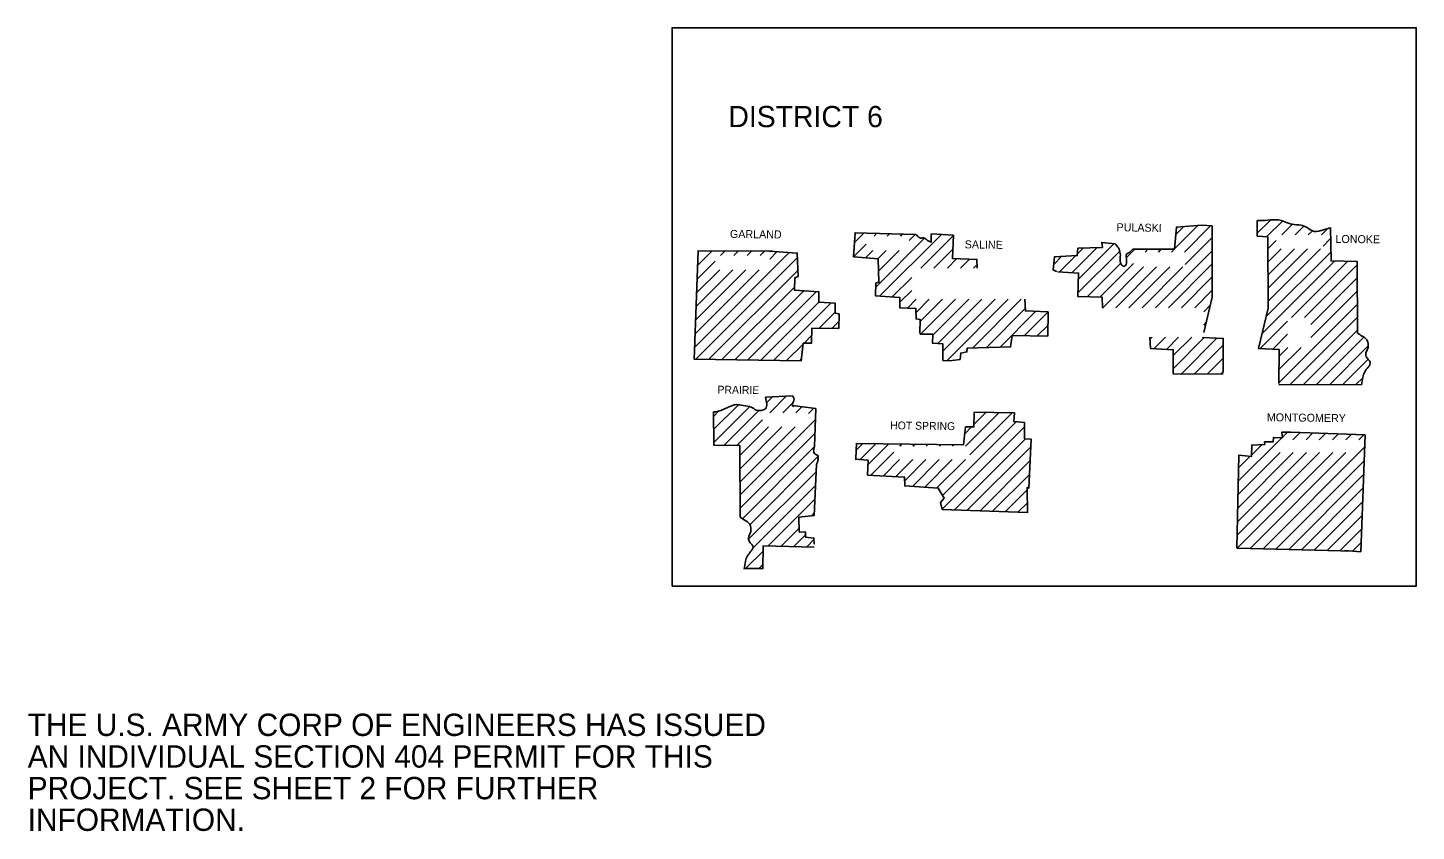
# Model space of a CAD drawing. Extents: x 76 to 6945, y -3933 to 2152.
# Drawn here: x 5990 to 6737, y -2877 to -2445 of the extents above; entities that cross this region are included whole.
import ezdxf

# ---------------------------------------------------------------- set-up
doc = ezdxf.new("R2010")
doc.units = 0
doc.layers.add('R_Draft', color=7, linetype='Continuous')

msp = doc.modelspace()

# ---------------------------------------------------------------- linework, layer by layer
at = {"layer": 'R_Draft'}
for p, q in [((6475.91, -2560.12), (6475.91, -2555.72)), ((6442.11, -2677.32), (6435.01, -2676.62))]:
    msp.add_line(p, q, dxfattribs=at)
msp.add_lwpolyline([(6336.61, -2744.92), (6336.61, -2444.92), (6736.61, -2444.92), (6736.61, -2744.92)], close=True, dxfattribs=at)
for points in [[(6584.21, -2563.92), (6606.71, -2563.82), (6607.71, -2552.02), (6621.11, -2551.02)], [(6606.71, -2563.72), (6619.31, -2551.12)], [(6607.41, -2556.02), (6611.71, -2551.72)], [(6612.11, -2565.42), (6626.11, -2551.42)], [(6621.11, -2551.02), (6626.91, -2551.42), (6627.01, -2589.62), (6622.41, -2608.72)], [(6651.11, -2555.32), (6658.21, -2548.32)], [(6651.11, -2556.92), (6651.11, -2548.52)], [(6656.21, -2557.32), (6664.71, -2548.82)], [(6664.41, -2556.22), (6670.11, -2550.52)], [(6671.51, -2556.22), (6676.11, -2551.62)], [(6690.61, -2552.32), (6690.81, -2570.22), (6704.91, -2570.52), (6705.01, -2608.92)], [(6434.11, -2567.92), (6435.01, -2555.02), (6467.71, -2556.02)], [(6434.61, -2560.32), (6439.81, -2555.12)], [(6445.21, -2556.82), (6446.71, -2555.32)], [(6446.11, -2584.22), (6472.11, -2558.12)], [(6448.31, -2589.02), (6481.21, -2556.12)], [(6452.31, -2556.82), (6453.41, -2555.62)], [(6459.41, -2556.82), (6460.31, -2555.82)], [(6464.01, -2559.22), (6467.21, -2556.02)], [(6470.41, -2574.02), (6487.71, -2556.72)], [(6475.91, -2555.72), (6487.81, -2556.42), (6487.41, -2568.92), (6500.51, -2569.42), (6500.61, -2574.02)], [(6612.41, -2572.12), (6626.91, -2557.62)], [(6662.81, -2636.12), (6662.91, -2617.72), (6651.81, -2617.22), (6657.01, -2595.52), (6656.91, -2557.32), (6651.11, -2556.92)], [(6656.91, -2563.72), (6661.41, -2559.22)], [(6678.61, -2556.22), (6680.71, -2554.12)], [(6685.61, -2556.22), (6688.71, -2553.12)], [(6686.61, -2562.22), (6690.61, -2558.22)], [(6348.41, -2623.02), (6350.61, -2564.72), (6390.61, -2564.92)], [(6348.71, -2616.62), (6399.61, -2565.72)], [(6350.31, -2572.62), (6358.11, -2564.82)], [(6350.61, -2565.32), (6351.11, -2564.72)], [(6362.71, -2567.32), (6365.21, -2564.82)], [(6369.81, -2567.32), (6372.21, -2564.92)], [(6376.91, -2567.32), (6379.31, -2564.92)], [(6383.91, -2567.32), (6386.31, -2564.92)], [(6389.01, -2564.92), (6403.91, -2566.02), (6404.31, -2578.62), (6402.61, -2579.22), (6402.41, -2585.92), (6415.51, -2586.82), (6415.51, -2592.32), (6424.21, -2592.82), (6424.31, -2598.32), (6426.41, -2598.62), (6426.31, -2606.52)], [(6389.11, -2569.22), (6393.01, -2565.32)], [(6434.11, -2567.92), (6440.91, -2561.12)], [(6440.61, -2568.52), (6444.61, -2564.52)], [(6447.21, -2569.02), (6451.71, -2564.52)], [(6447.71, -2575.52), (6458.71, -2564.52)], [(6475.91, -2560.12), (6475.91, -2560.22)], [(6477.41, -2574.02), (6487.51, -2563.92)], [(6543.21, -2576.02), (6543.21, -2575.92), (6541.41, -2575.02), (6542.11, -2568.02), (6554.41, -2567.32), (6554.81, -2563.42), (6567.91, -2562.92), (6567.61, -2560.22), (6574.81, -2561.02)], [(6544.91, -2576.02), (6553.71, -2567.22)], [(6551.61, -2576.42), (6564.91, -2563.12)], [(6554.51, -2566.42), (6557.61, -2563.32)], [(6554.71, -2587.42), (6577.21, -2565.02)], [(6555.01, -2580.02), (6574.01, -2561.02)], [(6580.71, -2568.52), (6585.31, -2563.92)], [(6590.91, -2565.42), (6592.41, -2563.92)], [(6596.41, -2595.32), (6626.91, -2564.72)], [(6598.01, -2565.42), (6599.41, -2563.92)], [(6605.01, -2565.42), (6606.51, -2563.92)], [(6656.01, -2600.02), (6690.81, -2565.22)], [(6657.01, -2591.82), (6685.11, -2563.72)], [(6657.01, -2584.82), (6678.11, -2563.72)], [(6657.01, -2577.72), (6671.11, -2563.72)], [(6657.01, -2570.72), (6664.01, -2563.72)], [(6349.41, -2623.02), (6403.91, -2568.52)], [(6350.11, -2579.92), (6359.71, -2570.32)], [(6469.81, -2609.02), (6469.91, -2601.62), (6467.81, -2601.32), (6467.71, -2595.82), (6459.01, -2595.32), (6459.01, -2589.82), (6445.91, -2588.92), (6446.11, -2582.22), (6447.81, -2581.62), (6447.41, -2569.02), (6434.11, -2568.02)], [(6484.61, -2574.02), (6489.51, -2569.02)], [(6491.61, -2574.02), (6496.41, -2569.22)], [(6498.71, -2574.02), (6500.51, -2572.22)], [(6541.71, -2572.22), (6546.21, -2567.72)], [(6559.81, -2589.42), (6577.91, -2571.32)], [(6566.61, -2589.72), (6584.71, -2571.62)], [(6568.01, -2595.42), (6568.11, -2595.32), (6590.01, -2573.42)], [(6575.11, -2595.32), (6597.01, -2573.42)], [(6582.21, -2595.32), (6604.11, -2573.42)], [(6589.31, -2595.32), (6611.21, -2573.42)], [(6603.41, -2595.32), (6626.91, -2571.82)], [(6653.71, -2609.32), (6692.71, -2570.32)], [(6669.61, -2600.52), (6699.61, -2570.52)], [(6676.61, -2600.52), (6704.91, -2572.22)], [(6349.01, -2609.32), (6383.41, -2574.92)], [(6349.21, -2602.02), (6376.31, -2574.92)], [(6349.51, -2594.62), (6369.31, -2574.92)], [(6349.81, -2587.32), (6362.21, -2574.92)], [(6356.41, -2623.02), (6404.21, -2575.32)], [(6454.91, -2589.52), (6465.41, -2579.02)], [(6568.01, -2595.32), (6567.81, -2589.72), (6554.71, -2589.22), (6555.11, -2576.72), (6543.91, -2576.02)], [(6610.51, -2595.32), (6626.91, -2578.82)], [(6679.91, -2604.32), (6704.91, -2579.32)], [(6363.41, -2623.22), (6402.41, -2584.22)], [(6370.41, -2623.32), (6407.41, -2586.22)], [(6377.31, -2623.42), (6414.01, -2586.72)], [(6459.01, -2592.42), (6465.41, -2586.02)], [(6617.61, -2595.32), (6626.91, -2585.92)], [(6679.91, -2611.42), (6704.91, -2586.42)], [(6384.31, -2623.52), (6415.51, -2592.32)], [(6391.31, -2623.52), (6422.11, -2592.72)], [(6463.11, -2595.52), (6467.81, -2590.82)], [(6467.81, -2597.82), (6474.81, -2590.82)], [(6469.91, -2602.82), (6481.91, -2590.82)], [(6470.21, -2609.62), (6489.01, -2590.82)], [(6476.81, -2610.02), (6496.11, -2590.82)], [(6479.41, -2614.52), (6503.11, -2590.82)], [(6482.21, -2618.72), (6510.21, -2590.82)], [(6484.31, -2623.82), (6517.31, -2590.82)], [(6498.11, -2617.02), (6524.31, -2590.82)], [(6505.41, -2616.82), (6526.41, -2595.82)], [(6526.21, -2590.82), (6526.51, -2597.02), (6538.71, -2597.62), (6538.61, -2610.62)], [(6622.41, -2597.52), (6625.91, -2594.02)], [(6662.91, -2635.52), (6704.91, -2593.52)], [(6415.51, -2606.42), (6424.21, -2597.72)], [(6422.51, -2606.52), (6426.31, -2602.72)], [(6512.71, -2616.62), (6531.91, -2597.32)], [(6525.91, -2610.52), (6538.71, -2597.62)], [(6622.41, -2604.62), (6623.71, -2603.32)], [(6652.91, -2617.12), (6667.51, -2602.52)], [(6668.71, -2636.72), (6704.91, -2600.52)], [(6426.31, -2606.52), (6411.71, -2606.32), (6411.61, -2614.32), (6407.11, -2614.32), (6406.01, -2623.82), (6348.41, -2623.02)], [(6407.61, -2614.32), (6411.61, -2610.32)], [(6485.81, -2623.92), (6482.21, -2623.62), (6482.21, -2614.82), (6476.61, -2614.42), (6476.81, -2609.62), (6469.81, -2609.52)], [(6538.61, -2610.62), (6519.51, -2610.32), (6518.61, -2616.42), (6495.31, -2617.12), (6495.11, -2619.12), (6491.81, -2619.72), (6491.41, -2623.12), (6485.81, -2623.92)], [(6532.91, -2610.52), (6538.61, -2604.82)], [(6605.91, -2630.92), (6606.01, -2617.92), (6593.81, -2617.32), (6593.51, -2611.12)], [(6593.61, -2612.22), (6594.71, -2611.12)], [(6595.51, -2617.42), (6601.81, -2611.12)], [(6602.31, -2617.72), (6608.91, -2611.12)], [(6605.91, -2628.12), (6622.71, -2611.42)], [(6606.01, -2621.02), (6615.91, -2611.12)], [(6610.21, -2631.02), (6629.51, -2611.62)], [(6621.91, -2611.12), (6621.81, -2611.32), (6632.91, -2611.82), (6632.81, -2630.22)], [(6659.71, -2617.42), (6667.51, -2609.62)], [(6675.81, -2636.72), (6704.91, -2607.62)], [(6682.91, -2636.72), (6708.31, -2611.32)], [(6398.21, -2623.72), (6407.01, -2614.92)], [(6617.31, -2631.02), (6632.81, -2615.42)], [(6662.91, -2628.42), (6674.71, -2616.62)], [(6662.91, -2621.32), (6667.61, -2616.62)], [(6690.01, -2636.72), (6710.61, -2616.02)], [(6405.21, -2623.82), (6406.11, -2622.82)], [(6624.41, -2630.92), (6632.81, -2622.52)], [(6697.11, -2636.62), (6710.81, -2622.92)], [(6610.71, -2631.02), (6605.91, -2630.92)], [(6632.81, -2630.82), (6610.71, -2631.02)], [(6631.51, -2630.92), (6632.81, -2629.52)], [(6704.21, -2636.62), (6707.91, -2632.92)], [(6707.21, -2636.62), (6662.81, -2636.82)], [(6358.91, -2660.82), (6372.11, -2647.62)], [(6359.01, -2667.72), (6378.21, -2648.52)], [(6386.81, -2643.42), (6401.31, -2642.72)], [(6387.81, -2646.02), (6390.51, -2643.32)], [(6389.11, -2651.82), (6398.01, -2642.92)], [(6396.11, -2651.82), (6401.81, -2646.12)], [(6401.31, -2647.92), (6413.81, -2649.52), (6413.11, -2669.92)], [(6403.21, -2651.82), (6406.41, -2648.62)], [(6358.81, -2653.82), (6362.01, -2650.62)], [(6373.21, -2707.82), (6373.11, -2669.42), (6359.01, -2669.12), (6358.81, -2651.22)], [(6364.61, -2669.22), (6383.21, -2650.62)], [(6371.41, -2669.42), (6385.31, -2655.52)], [(6409.91, -2652.12), (6412.71, -2649.42)], [(6409.91, -2659.22), (6413.61, -2655.52)], [(6435.71, -2668.32), (6493.31, -2668.92), (6494.41, -2659.42), (6498.91, -2659.42), (6499.01, -2651.42), (6520.61, -2651.72), (6520.41, -2656.52), (6526.01, -2656.92), (6526.01, -2665.72), (6529.61, -2666.02), (6528.41, -2692.22), (6527.51, -2691.92), (6527.61, -2705.52)], [(6482.01, -2696.22), (6521.51, -2656.72)], [(6494.41, -2669.72), (6512.51, -2651.62)], [(6496.71, -2674.42), (6519.51, -2651.72)], [(6498.91, -2658.12), (6505.51, -2651.52)], [(6373.11, -2674.82), (6388.51, -2659.42)], [(6373.21, -2695.92), (6409.71, -2659.42)], [(6373.21, -2688.82), (6402.71, -2659.42)], [(6373.21, -2681.82), (6395.61, -2659.42)], [(6373.21, -2703.02), (6413.31, -2662.92)], [(6481.81, -2703.52), (6526.01, -2659.32)], [(6494.01, -2663.12), (6497.61, -2659.42)], [(6640.19, -2724.51), (6641.29, -2674.61), (6648.09, -2675.21), (6648.19, -2669.11), (6655.19, -2668.91), (6655.09, -2667.31), (6659.79, -2667.31), (6659.89, -2665.11), (6664.69, -2665.21), (6664.29, -2662.21), (6669.29, -2662.11)], [(6664.59, -2665.01), (6667.39, -2662.21)], [(6669.29, -2662.11), (6709.09, -2663.61)], [(6670.29, -2666.31), (6674.29, -2662.31)], [(6677.39, -2666.31), (6681.09, -2662.61)], [(6684.49, -2666.31), (6687.99, -2662.81)], [(6691.59, -2666.31), (6694.79, -2663.11)], [(6698.69, -2666.31), (6701.59, -2663.41)], [(6705.69, -2666.31), (6708.39, -2663.61)], [(6709.09, -2663.61), (6706.79, -2726.41)], [(6374.71, -2708.62), (6412.71, -2670.52)], [(6435.41, -2676.42), (6435.71, -2668.12)], [(6435.61, -2671.92), (6439.21, -2668.32)], [(6437.81, -2676.82), (6446.21, -2668.42)], [(6442.11, -2679.62), (6453.21, -2668.42)], [(6459.11, -2669.72), (6460.21, -2668.52)], [(6466.11, -2669.72), (6467.21, -2668.62)], [(6473.21, -2669.72), (6474.11, -2668.82)], [(6480.31, -2669.72), (6481.11, -2668.92)], [(6487.41, -2669.72), (6488.11, -2668.92)], [(6488.51, -2703.92), (6526.61, -2665.72)], [(6495.31, -2704.12), (6529.41, -2670.12)], [(6640.99, -2688.61), (6663.09, -2666.51)], [(6648.19, -2674.31), (6653.59, -2669.01)], [(6654.29, -2724.81), (6708.89, -2670.21)], [(6655.09, -2667.41), (6655.29, -2667.31)], [(6663.29, -2666.31), (6664.39, -2665.21)], [(6378.61, -2711.82), (6415.01, -2675.32)], [(6527.61, -2705.32), (6481.81, -2703.72), (6480.91, -2700.02), (6482.81, -2697.62), (6479.71, -2692.22), (6461.71, -2691.12), (6461.61, -2686.32), (6441.71, -2685.22), (6442.11, -2677.32)], [(6443.51, -2685.32), (6455.81, -2672.92)], [(6450.21, -2685.62), (6458.91, -2676.92)], [(6456.91, -2686.02), (6466.01, -2676.92)], [(6461.71, -2688.32), (6473.11, -2676.92)], [(6465.81, -2691.32), (6480.21, -2676.92)], [(6472.41, -2691.72), (6487.21, -2676.92)], [(6479.01, -2692.12), (6494.31, -2676.92)], [(6502.21, -2704.42), (6529.01, -2677.52)], [(6640.29, -2724.61), (6640.39, -2724.51), (6691.79, -2673.21)], [(6640.39, -2717.51), (6684.69, -2673.21)], [(6640.49, -2710.31), (6677.59, -2673.21)], [(6640.69, -2703.01), (6670.49, -2673.21)], [(6640.79, -2695.81), (6663.39, -2673.21)], [(6641.09, -2681.41), (6647.39, -2675.11)], [(6647.29, -2724.71), (6698.79, -2673.21)], [(6661.09, -2725.01), (6708.59, -2677.61)], [(6377.71, -2719.72), (6414.01, -2683.42)], [(6414.21, -2679.52), (6413.01, -2706.92), (6404.81, -2707.82), (6405.01, -2715.92), (6408.31, -2715.82), (6408.41, -2718.62), (6412.91, -2719.12), (6413.01, -2722.42)], [(6508.91, -2704.72), (6528.71, -2684.92)], [(6668.09, -2725.21), (6708.29, -2684.91)], [(6380.21, -2724.32), (6413.71, -2690.82)], [(6515.71, -2704.92), (6527.51, -2693.22)], [(6674.89, -2725.41), (6707.99, -2692.31)], [(6388.31, -2723.22), (6413.41, -2698.22)], [(6522.51, -2705.22), (6527.61, -2700.22)], [(6681.79, -2725.51), (6707.79, -2699.61)], [(6411.51, -2707.12), (6413.01, -2705.62)], [(6688.79, -2725.71), (6707.49, -2706.91)], [(6395.21, -2723.42), (6405.01, -2713.72)], [(6695.59, -2725.91), (6707.19, -2714.31)], [(6413.01, -2723.92), (6385.61, -2723.22), (6385.41, -2735.52), (6375.41, -2735.52)], [(6402.11, -2723.62), (6408.41, -2717.32)], [(6409.01, -2723.82), (6413.01, -2719.72)], [(6702.59, -2726.01), (6706.89, -2721.61)], [(6376.11, -2735.42), (6385.71, -2725.92)], [(6703.09, -2726.11), (6640.39, -2724.51)], [(6698.09, -2726.01), (6698.09, -2725.81), (6706.79, -2726.41)], [(6383.21, -2735.42), (6385.41, -2733.22)]]:
    msp.add_lwpolyline(points, dxfattribs=at)
for points in [[(6651.31, -2548.52), (6656.91, -2548.32), (6662.41, -2548.12), (6665.91, -2549.12), (6669.91, -2550.42), (6674.61, -2551.02), (6677.91, -2552.32), (6681.81, -2554.32), (6686.81, -2553.42), (6690.61, -2552.42)], [(6467.71, -2556.02), (6468.91, -2557.12), (6470.21, -2557.92), (6471.81, -2557.82), (6473.31, -2558.72), (6475.91, -2560.12)], [(6574.81, -2561.02), (6576.51, -2563.22), (6577.51, -2566.22), (6577.51, -2569.62), (6578.31, -2572.42), (6579.91, -2573.02), (6580.91, -2570.62), (6580.71, -2568.22), (6580.71, -2566.82), (6582.41, -2565.62), (6584.21, -2563.92)], [(6705.01, -2608.92), (6707.51, -2610.62), (6710.11, -2612.62), (6710.81, -2615.32), (6710.61, -2617.22), (6709.81, -2618.82), (6709.61, -2621.32), (6710.81, -2623.12), (6711.91, -2624.62), (6710.81, -2627.32), (6708.91, -2629.82), (6707.91, -2632.62), (6707.21, -2636.82)], [(6358.81, -2651.32), (6358.91, -2651.32), (6364.01, -2650.02), (6367.31, -2648.62), (6371.11, -2647.42), (6374.91, -2647.92), (6379.21, -2648.72), (6381.91, -2650.32), (6386.81, -2649.62), (6386.81, -2643.42)], [(6401.41, -2642.72), (6402.21, -2644.32), (6401.91, -2645.72), (6401.31, -2647.92), (6401.81, -2648.62)], [(6413.11, -2669.92), (6412.71, -2671.92), (6413.51, -2674.02), (6414.91, -2674.72), (6415.11, -2676.72), (6414.61, -2678.72), (6414.21, -2679.52)], [(6375.41, -2735.72), (6376.11, -2731.52), (6377.11, -2728.72), (6379.01, -2726.22), (6380.11, -2723.52), (6379.01, -2722.02), (6377.81, -2720.22), (6378.01, -2717.72), (6378.81, -2716.12), (6379.01, -2714.22), (6378.31, -2711.52), (6375.71, -2709.52), (6373.21, -2707.82)]]:
    msp.add_spline(points, degree=3, dxfattribs=at)

# ---------------------------------------------------------------- texts
for s, height, p in [('DISTRICT 6', 11.4, (6366.91, -2498.32)), ('THE U.S. ARMY CORP OF ENGINEERS HAS ISSUED', 12, (5990.27, -2825.43)), ('AN INDIVIDUAL SECTION 404 PERMIT FOR THIS', 12, (5990.27, -2842.43)), ('PROJECT. SEE SHEET 2 FOR FURTHER', 12, (5990.27, -2859.43)), ('INFORMATION.', 12, (5990.27, -2876.43))]:
    msp.add_text(s, height=height, dxfattribs=at).set_placement(p)
for s, height, rotation, p in [('PULASKI', 4.301, 359.05305, (6575.51, -2554.22)), ('GARLAND', 4.301, 359.36576, (6367.71, -2557.82)), ('SALINE', 4.301, 359.14914, (6493.91, -2563.42)), ('LONOKE', 4.301, 359.49742, (6693.21, -2560.52)), ('PRAIRIE', 4.201, 359.21158, (6361.01, -2641.42)), ('HOT SPRING', 4.201, 359.22157, (6453.81, -2660.62)), ('MONTGOMERY', 4.301, 359.29442, (6656.29, -2656.31))]:
    msp.add_text(s, height=height, rotation=rotation, dxfattribs=at).set_placement(p)

doc.saveas('drawing.dxf')
